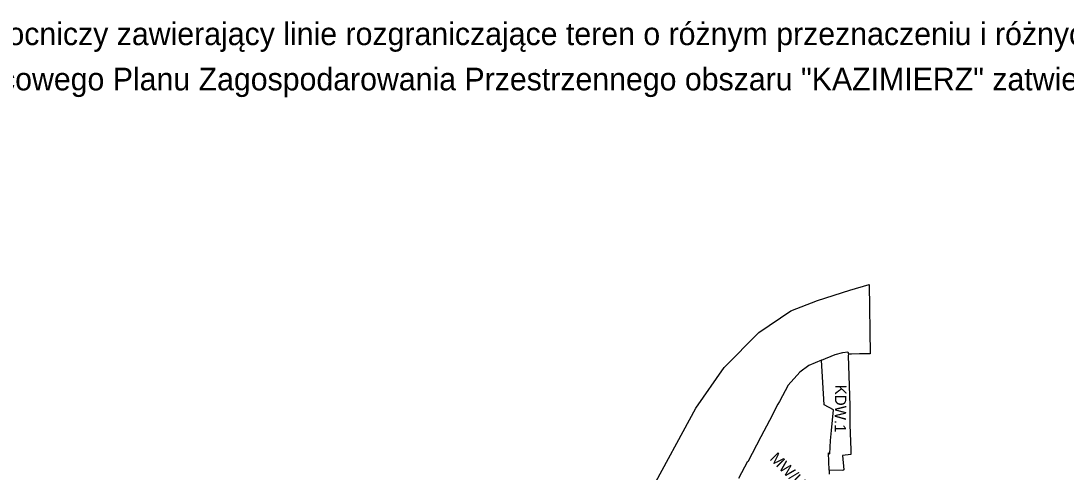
# Model space of a CAD drawing. Extents: x 7423835 to 7425280, y 5546086 to 5547600.
# Drawn here: x 7424204 to 7424758, y 5547361 to 5547600 of the extents above; entities that cross this region are included whole.
import ezdxf

# ---------------------------------------------------------------- set-up
doc = ezdxf.new("R2010")
doc.units = 0
for name, color, linetype in [('info', 7, 'Continuous'), ('linie rozgraniczające', 7, 'Continuous'), ('nieprzekraczalne linie zabudowy', 7, 'Continuous'), ('obowiazujace linie zabudowy', 7, 'Continuous'), ('przeznaczenia terenów', 7, 'Continuous')]:
    doc.layers.add(name, color=color, linetype=linetype)

msp = doc.modelspace()

# ---------------------------------------------------------------- linework, layer by layer
at = {"layer": 'linie rozgraniczające'}
for p, q in [((7424626.63, 5547451.7), (7424643.74, 5547457.25)), ((7424643.74, 5547457.25), (7424654.11, 5547460.15)), ((7424612.59, 5547446.29), (7424626.63, 5547451.7))]:
    msp.add_line(p, q, dxfattribs=at)
for points in [[(7424654.11, 5547460.15), (7424654.57, 5547423.45), (7424652.14, 5547423.42), (7424648.96, 5547423.37), (7424644.67, 5547423.23), (7424643.05, 5547423.17)], [(7424577.11, 5547416.18), (7424595.5, 5547434.76), (7424612.59, 5547446.29)], [(7424628.8, 5547419.99), (7424636.06, 5547423.1), (7424640.03, 5547424.11), (7424642.8, 5547424.4), (7424643.05, 5547423.17)], [(7424628.8, 5547419.99), (7424622.09, 5547417.25), (7424617.21, 5547413.73), (7424611.06, 5547406.78), (7424606.45, 5547398.21), (7424605.67, 5547396.65), (7424601.2, 5547388.08), (7424596.65, 5547379.47), (7424592.05, 5547370.53), (7424589.78, 5547366.16), (7424589.6, 5547366.25), (7424584.84, 5547357.21)], [(7424632.77, 5547361.71), (7424632.77, 5547361.71), (7424632.77, 5547361.71), (7424632.77, 5547361.71), (7424632.43, 5547370.87), (7424633.22, 5547370.44), (7424633.45, 5547377.52), (7424634, 5547382.69), (7424635.07, 5547393.72), (7424630.26, 5547396.44), (7424628.8, 5547419.99)], [(7424643.05, 5547423.17), (7424642.89, 5547422.5), (7424643.71, 5547395.92), (7424643.86, 5547385.84), (7424644.23, 5547372.46), (7424644.38, 5547370.07), (7424639.91, 5547369.46), (7424640.57, 5547361.89), (7424640.12, 5547361.59), (7424632.77, 5547361.71), (7424632.86, 5547359.66)], [(7424537.6, 5547349.36), (7424562.07, 5547394.62), (7424577.11, 5547416.18)]]:
    msp.add_lwpolyline(points, dxfattribs=at)
at = {"layer": 'nieprzekraczalne linie zabudowy'}
msp.add_lwpolyline([(7424632.77, 5547361.71), (7424632.77, 5547361.71), (7424632.77, 5547361.71), (7424632.77, 5547361.71), (7424632.43, 5547370.87), (7424633.22, 5547370.44), (7424633.45, 5547377.52), (7424634, 5547382.69), (7424635.07, 5547393.72), (7424630.26, 5547396.44), (7424628.8, 5547419.99)], dxfattribs=at)
at = {"layer": 'obowiazujace linie zabudowy'}
msp.add_lwpolyline([(7424628.8, 5547419.99), (7424622.09, 5547417.25), (7424617.21, 5547413.73), (7424611.06, 5547406.78), (7424606.45, 5547398.21), (7424605.67, 5547396.65), (7424601.2, 5547388.08), (7424596.65, 5547379.47), (7424592.05, 5547370.53), (7424589.78, 5547366.16), (7424589.6, 5547366.25), (7424584.84, 5547357.21)], dxfattribs=at)

# ---------------------------------------------------------------- texts
at = {"layer": 'info'}
for s, p in [('Materiał pomocniczy zawierający linie rozgraniczające teren o różnym przeznaczeniu i różnych warunkach zagospodarowania terenu, ', (7424104.44, 5547587.15)), ('opracowane w skali 1:1000 pochodzące z Miejscowego Planu Zagospodarowania Przestrzennego obszaru "KAZIMIERZ" zatwierdzonego uchwałą RMK Nr LXXXVIII/2145/17 z dnia 08 listopada 2017 r.', (7423854.32, 5547563.15))]:
    msp.add_text(s, height=12, dxfattribs=at).set_placement(p)
at = {"layer": 'przeznaczenia terenów'}
for s, rotation, p in [('KDW.1', 269.2728, (7424636.03, 5547407.1)), ('MW/U.1', 314.9764, (7424601.01, 5547367.52))]:
    msp.add_text(s, height=6, rotation=rotation, dxfattribs=at).set_placement(p)

doc.saveas('drawing.dxf')
